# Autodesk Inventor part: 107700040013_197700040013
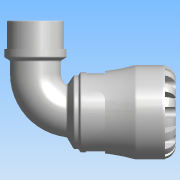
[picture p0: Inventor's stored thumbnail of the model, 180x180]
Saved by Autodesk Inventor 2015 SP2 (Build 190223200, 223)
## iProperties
Created: 2016-12
Part Number: 107700040013_197700040013
Material: PVC-Piping
Description: PLASSON 90° ELBOW WITH MALE INTEGRAL BRASS 40X1.1/4" SERIES 1
Document SubType Name: Modeling
Designer: KIM
Mass: 664.223 g
Surface Area: 733.008 cm^2
Volume: 474.445 cm^3
Density: 1.4 g/cm^3
Appearance: Smooth - White
Author: KIM
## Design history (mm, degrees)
derived "1077.ipt"
feature "Solid1::1077.ipt"
tag "TaggingFeature1"
body "Solid1"
other parameters: "d1" = 29.82, "d8" = 59.5, "d13" = 8, "d14" = 8, "d15" = 0, "d17" = 360 deg, "d19" = 8 deg, "d20" = 0.8, "d21" = 0.8, "d22" = 8 deg, "d24" = 0, "d26" = 360 deg, "d33" = 7, "d43" = 54.6, "d51" = 0.7, "d54" = 14, "d55" = 8.8, "d57" = 15.68, "d58" = 0, "d74" = 0, "d78" = 71, "d82" = 0.8, "d115" = 360 deg, "d207" = 90 deg, "d228" = 11.9, "d247" = 1.4, "d248" = 4.26, "d268" = 32.725, "d269" = 4.26, "d270" = 104, "d276" = 41.91, "d277" = 21, "d278" = 46.101, "d279" = 68, "d280" = 27.3, "d281" = 6.2865, "d283" = 37.719, "d286" = 0, "d287" = 0, "d288" = 29.337, "d290" = 8.4405, "d292" = 30 deg, "d294" = 4.191, "d296" = 30 deg, "l_" = 71, "A_" = 104, "A_1" = 68, "l_2" = 21, "R_" = 41.91, "d9" = 10, "d289" = 29.337
